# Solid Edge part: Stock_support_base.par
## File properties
Title: Stock Support Base
Author: Abhinav Rai
Template: Normal.par
Last saved by: Cadcim
Revision: 18
Application: Solid Edge
Material: aluminum
Accuracy: 0.99
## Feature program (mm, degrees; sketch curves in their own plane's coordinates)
sketch for "unnamed RevolvedProtrusion 1" plane through (0, 0, 0) normal (0, -1, 0) x-axis (1, 0, 0)
  line (0, 29.2468) -> (71.7103, 29.2468)
  line (71.7103, 29.2468) -> (71.7103, 19.7218)
  line (71.7103, 19.7218) -> (165.1, -256.5032)
  line (165.1, -256.5032) -> (215.9, -256.5032)
  line (215.9, -256.5032) -> (215.9, -281.9032)
  line (215.9, -281.9032) -> (156.9298, -281.9032)
  line (156.9298, -281.9032) -> (85.052, -69.3053)
  arc centre (73.021, -73.3729) radius 12.7 from (60.325, -73.0538) to (85.052, -69.3053) cw
  line (60.325, -73.0538) -> (57.15, -199.3532)
  line (57.15, -199.3532) -> (0, -199.3532)
  line (0, 29.2468) -> (0, -199.3532)
revolve "unnamed RevolvedProtrusion 1" add full turn 360 deg
sketch for "unnamed Hole 1" plane through (0, 0, 29.2468) normal (0, 0, 1) x-axis (1, 0, 0)
  hole centre (0, 0) bore radius 38.1
hole "unnamed Hole 1" through
sketch for "ExtrudedProtrusion_2" plane through (0, 0, -256.5032) normal (0, 0, 1) x-axis (0, 1, 0)
  arc centre (0, -119.2664) radius 41.0756 from (-18.7686, -155.8034) to (18.7686, -155.8034) ccw
  line (-18.7686, -197.1314) -> (-18.7686, -155.8034)
  arc centre (0, -197.1314) radius 18.7686 from (18.7686, -197.1314) to (-18.7686, -197.1314) cw
  line (18.7686, -197.1314) -> (18.7686, -155.8034)
extrude "ExtrudedProtrusion_2" add finite 12.7 along +normal
sketch for "unnamed Hole 2" plane through (187.8036, 0, -243.8032) normal (0, 0, 1) x-axis (1, 0, 0)
hole "unnamed Hole 2" through
fillet "Round_4" radius 3.175
pattern "unnamed Pattern 1" of "ExtrudedProtrusion_2", "unnamed Hole 2", "Round_4"
pattern "unnamed Pattern 2"
sketch for "ExtrudedProtrusion_3" plane through (0, -134.62, 0) normal (0, -1, 0) x-axis (1, 0, 0)
  circle centre (0, -2.5032) radius 19.05
extrude "ExtrudedProtrusion_3" add  Plane_Distance = 134.62 mm
adv blend "unnamed AdvBlend 1"
sketch for "ExtrudedProtrusion_4" plane through (0, -134.62, -2.5032) normal (0, -1, 0) x-axis (1, 0, 0)
  circle centre (0, -3.81) radius 22.225
extrude "ExtrudedProtrusion_4" add finite 9.525 along +normal
mirror "unnamed Mirror 1" of "ExtrudedProtrusion_4", "unnamed AdvBlend 1", "ExtrudedProtrusion_3" about plane through (0, 0, 0) normal (0, -1, 0)
extrude "unnamed Protrusion 1" add
adv blend "unnamed AdvBlend 2"
extrude "unnamed Protrusion 2" add finite 9.525
sketch for "ExtrudedProtrusion_7" plane through (104.775, 0, 0) normal (1, 0, 0) x-axis (0, 1, 0)
  circle centre (0, -167.6032) radius 19.05
extrude "ExtrudedProtrusion_7" add finite 41.275 along +normal  Plane_Distance = 104.775 mm
sketch for "unnamed Hole 3" plane through (146.05, 0, -167.6032) normal (1, 0, 0) x-axis (0, 1, 0)
  hole centre (0, 0) bore radius 7.9375
hole "unnamed Hole 3" through
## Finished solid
Body 1: solid body, 54 faces, 95 edges, 41 vertices.
  Faces by surface: plane 26, cylinder 19, torus 4, cone 3, blend 2
  Edges by curve: circle 57, intersection 20, line 18
Bounding box of the edges (mm; curved faces can reach further): 431.800 x 431.800 x 311.150, from (-215.9, -215.9, -281.9032) to (215.9, 215.9, 29.2468).
Cylindrical faces by radius (mm): R7.9375 x1, R11.1125 x3, R15.875 x3, R18.7686 x3, R19.05 x4, R22.225 x2, R38.1 x1, R71.7103 x1, R215.9 x1
Conical faces (half-angle, radius in mm at the cone's reference point): 1.44 deg R60.325 x1, 18.68 deg R71.7103 x1, 18.68 deg R156.9298 x1
Toroidal faces (ring radius, tube radius in mm): R73.021 r12.7 x1, R163.0843 r3.175 x3
Planar faces by outward normal: +x 1, +y 4, +z 10, -x 1, -y 4, -z 2, oblique 4
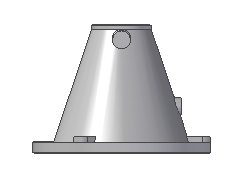
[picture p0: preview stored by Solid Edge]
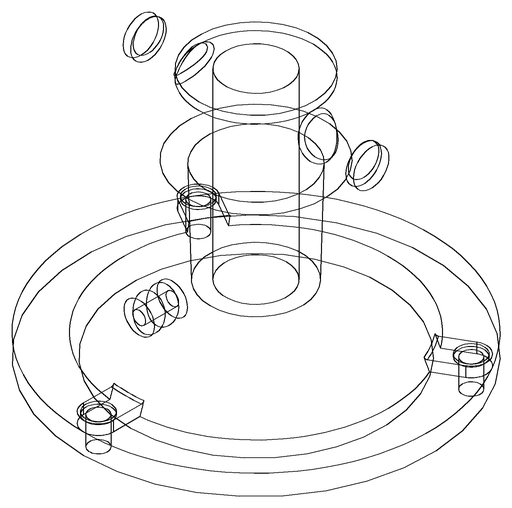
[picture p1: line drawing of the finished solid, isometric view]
